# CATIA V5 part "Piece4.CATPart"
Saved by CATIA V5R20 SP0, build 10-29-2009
Part number: Piece4
Bounding box of the stored display mesh (mm): x 0 to 100, y 228.37 to 270.114, z -8.418 to 298.759
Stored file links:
  C:\Users\Lambert\Desktop\IAO\Piece4.CATPart
  C:\Users\Lambert\Desktop\IAO\Produit1.CATProduct
  C:\Users\Lambert\Desktop\IAO\skl_general.CATPart
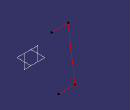
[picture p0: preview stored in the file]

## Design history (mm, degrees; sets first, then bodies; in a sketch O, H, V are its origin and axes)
Set1
  DatumPoint1 "F": linked copy from another document
  DatumPoint2 "E": linked copy from another document
  Plane1 "Plan_Ref": linked copy from another document
Set2
  Line1 "Bielle 4": type PtPt, FirstPoint DatumPoint1, SecondPoint DatumPoint2, Support Plane1
  Line2 "Axe_pivot_43": type Normal, RefPoint DatumPoint1, RefSkin Plane1, Start 0, End 100
  Line3 "Axe_pivot_42": type Normal, RefPoint DatumPoint2, RefSkin Plane1, Start 0, End 100
Body1 (main body)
